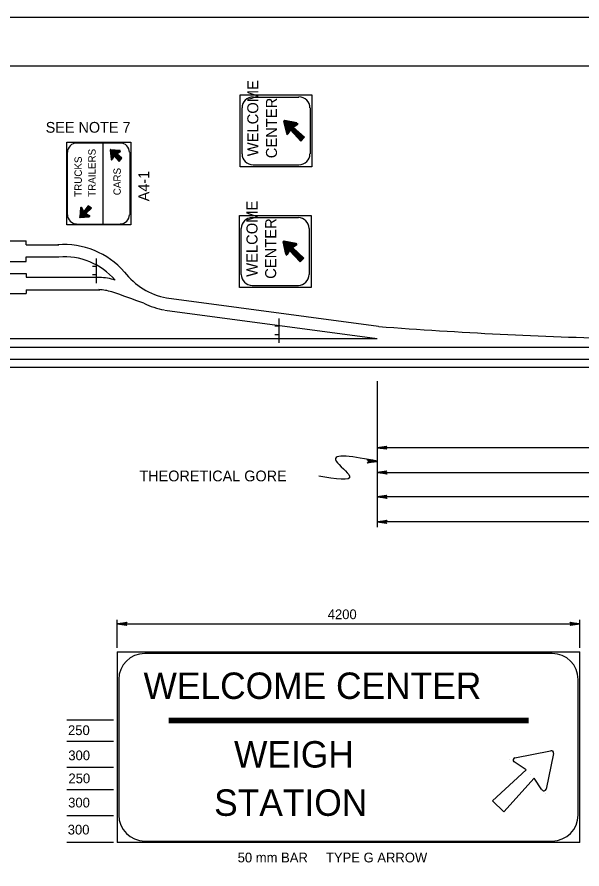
# Model space of a CAD drawing. Extents: x 638689 to 652291, y 298458 to 299646.
# Drawn here: x 651569.7 to 651743.8, y 299383.4 to 299645.7 of the extents above; entities that cross this region are included whole.
import ezdxf

# ---------------------------------------------------------------- set-up
doc = ezdxf.new("R2010")
doc.units = 0
for name, color, linetype in [('1', 7, 'Continuous'), ('2', 7, 'Continuous'), ('3', 7, 'Continuous'), ('PLT-BNDY', 7, 'Continuous')]:
    doc.layers.add(name, color=color, linetype=linetype)

# ---------------------------------------------------------------- blocks, each defined once
blk = doc.blocks.new('RARROW')
at = {"layer": '3'}
blk.add_lwpolyline([(-2.2695, 0.285), (-2.184875, 0.12075), (0, 0), (-2.2695, 0.285), (-2.38575, 0.384625), (0, 0), (-2.183125, -0.108), (-2.262875, -0.2705), (0, 0), (-2.38575, -0.379125), (-2.262875, -0.2705)], dxfattribs=at)

msp = doc.modelspace()

# ---------------------------------------------------------------- linework, layer by layer
at = {"layer": '1'}
msp.add_line((651426.31, 299630.75), (652212.31, 299630.75), dxfattribs=at)
at = {"layer": '2'}
for p, q in [((651642.44, 299621.12), (651656.56, 299621.12)), ((651651.81, 299613.87), (651651.81, 299613.87)), ((651651.94, 299613.62), (651652.81, 299609.87)), ((651655.94, 299613.12), (651652.19, 299613.87)), ((651654.81, 299611.87), (651656.19, 299612.75)), ((651656.56, 299613), (651656.56, 299613)), ((651653.19, 299609.75), (651653.94, 299611)), ((651653.94, 299611), (651653.94, 299611)), ((651653.94, 299611), (651657.19, 299607.5)), ((651654.81, 299611.87), (651654.81, 299611.87)), ((651658.31, 299608.75), (651654.81, 299611.87)), ((651588.06, 299607), (651601.56, 299607)), ((651596.31, 299582), (651596.31, 299607)), ((651652.94, 299609.37), (651652.94, 299609.37)), ((651657.19, 299607.5), (651658.31, 299608.75)), ((651598.44, 299604.75), (651598.69, 299602)), ((651601.44, 299604.62), (651598.56, 299604.87)), ((651598.56, 299604.75), (651598.56, 299604.75)), ((651600.44, 299603.62), (651601.44, 299604.25)), ((651601.44, 299604.37), (651601.44, 299604.37)), ((651601.69, 299604.37), (651601.69, 299604.37)), ((651601.69, 299604.37), (651601.69, 299604.37)), ((651598.81, 299602), (651598.81, 299602)), ((651598.81, 299601.62), (651598.81, 299601.62)), ((651598.81, 299601.62), (651598.81, 299601.62)), ((651599.69, 299603), (651599.06, 299602)), ((651599.69, 299603), (651599.69, 299603)), ((651599.69, 299603), (651601.19, 299601.25)), ((651600.06, 299603.37), (651600.06, 299603.37)), ((651600.44, 299603.62), (651600.44, 299603.62)), ((651602.06, 299602.25), (651600.44, 299603.62)), ((651601.19, 299601.25), (651602.06, 299602.25)), ((651602.06, 299602.25), (651602.06, 299602.25)), ((651601.19, 299601.25), (651601.19, 299601.25)), ((651660.56, 299599.62), (651638.44, 299599.62)), ((651656.56, 299600.12), (651642.44, 299600.12)), ((651589.31, 299587), (651589.06, 299584.25)), ((651589.56, 299587.25), (651589.56, 299587.25)), ((651589.56, 299587.25), (651589.56, 299587.25)), ((651589.56, 299587), (651589.56, 299587)), ((651590.31, 299585.87), (651589.69, 299587.12)), ((651591.69, 299587.62), (651590.31, 299585.87)), ((651590.94, 299585.25), (651592.69, 299586.87)), ((651591.69, 299587.62), (651591.69, 299587.62)), ((651592.69, 299586.87), (651591.69, 299587.62)), ((651592.69, 299586.87), (651592.69, 299586.87)), ((651589.06, 299584.12), (651589.06, 299584.12)), ((651589.06, 299584.12), (651589.06, 299584.12)), ((651589.19, 299584.25), (651589.19, 299584.25)), ((651589.19, 299584), (651591.94, 299584.25)), ((651590.31, 299585.87), (651590.31, 299585.87)), ((651590.56, 299585.62), (651590.56, 299585.62)), ((651590.94, 299585.25), (651590.94, 299585.25)), ((651590.94, 299585.25), (651591.94, 299584.62)), ((651591.94, 299584.5), (651591.94, 299584.5)), ((651592.19, 299584.5), (651592.19, 299584.5)), ((651592.19, 299584.5), (651592.19, 299584.5)), ((651642.19, 299584), (651656.44, 299584)), ((651587.69, 299581.75), (651585.81, 299581.75)), ((651588.06, 299582), (651601.56, 299582)), ((651596.81, 299581.75), (651595.44, 299581.75)), ((651549.94, 299576.87), (651572.56, 299576.87)), ((651572.56, 299575.62), (651572.56, 299576.87)), ((651572.56, 299575.62), (651582.56, 299575.62)), ((651651.56, 299576.75), (651651.56, 299576.75)), ((651651.69, 299576.5), (651652.56, 299572.75)), ((651655.69, 299576), (651651.94, 299576.75)), ((651654.56, 299574.75), (651655.81, 299575.62)), ((651656.31, 299575.87), (651656.31, 299575.87)), ((651652.94, 299572.62), (651653.69, 299573.87)), ((651653.69, 299573.87), (651653.69, 299573.87)), ((651653.69, 299573.87), (651656.94, 299570.37)), ((651654.56, 299574.75), (651654.56, 299574.75)), ((651658.06, 299571.5), (651654.56, 299574.75)), ((651549.94, 299570.5), (651572.56, 299570.5)), ((651572.56, 299570.5), (651572.56, 299571.87)), ((651572.56, 299571.87), (651582.56, 299571.87)), ((651594.19, 299563.75), (651594.19, 299571.37)), ((651652.69, 299572.25), (651652.69, 299572.25)), ((651656.94, 299570.37), (651658.06, 299571.5)), ((651594.19, 299568.87), (651592.94, 299568.87)), ((651549.94, 299566.75), (651572.56, 299566.75)), ((651572.56, 299566.75), (651572.56, 299565.62)), ((651572.56, 299565.62), (651595.19, 299565.62)), ((651594.19, 299566.37), (651592.94, 299566.37)), ((651660.31, 299562.5), (651638.31, 299562.5)), ((651656.44, 299563), (651642.19, 299563)), ((651549.94, 299560.62), (651572.56, 299560.62)), ((651572.56, 299561.75), (651572.56, 299560.62)), ((651572.56, 299561.75), (651595.19, 299561.75)), ((651615.81, 299559.25), (651681.06, 299550.5)), ((651615.31, 299555.5), (651615.31, 299555.5)), ((651615.31, 299555.5), (651680.69, 299546.75)), ((651650.44, 299545.37), (651650.44, 299552.87)), ((651650.44, 299550.5), (651649.19, 299550.5)), ((651441.81, 299546.75), (651680.69, 299546.75)), ((651650.44, 299547.87), (651649.19, 299547.87)), ((651680.69, 299546.75), (651680.69, 299546.75)), ((651680.69, 299546.75), (651680.69, 299546.75)), ((651429.31, 299544.12), (652211.31, 299544.12)), ((651429.31, 299540.37), (652211.31, 299540.37)), ((651429.31, 299537.87), (652211.31, 299537.87)), ((651680.69, 299533.62), (651680.69, 299488.62)), ((651917.06, 299513.12), (651680.69, 299513.12)), ((651680.69, 299505.5), (652031.94, 299505.5)), ((652084.69, 299498), (651680.69, 299498)), ((652137.56, 299490.25), (651680.69, 299490.25)), ((651600.58, 299451.48), (651600.58, 299460.1)), ((651743.08, 299451.48), (651743.08, 299460.1)), ((651600.58, 299458.85), (651743.08, 299458.85)), ((651600.58, 299450.23), (651743.08, 299450.23)), ((651600.58, 299450.23), (651600.58, 299391.48)), ((651734.58, 299449.73), (651609.08, 299449.73)), ((651743.08, 299391.48), (651743.08, 299450.23)), ((651601.08, 299441.73), (651601.08, 299399.98)), ((651742.58, 299399.98), (651742.58, 299441.73)), ((651599.45, 299429.23), (651585.09, 299429.23)), ((651616.45, 299429.85), (651727.33, 299429.85)), ((651616.45, 299429.6), (651727.33, 299429.6)), ((651616.45, 299429.23), (651727.33, 299429.23)), ((651616.45, 299428.98), (651727.33, 299428.98)), ((651616.45, 299428.73), (651727.33, 299428.73)), ((651616.45, 299428.48), (651727.33, 299428.48)), ((651599.45, 299422.6), (651585.09, 299422.6)), ((651723.08, 299417.6), (651734.08, 299419.73)), ((651734.95, 299418.98), (651732.7, 299407.98)), ((651734.95, 299418.98), (651732.7, 299407.98)), ((651735.08, 299419.98), (651735.08, 299419.98)), ((651721.58, 299417.23), (651721.58, 299417.23)), ((651726.58, 299413.85), (651722.83, 299416.35)), ((651726.58, 299413.85), (651722.83, 299416.35)), ((651599.45, 299414.6), (651585.09, 299414.6)), ((651716.2, 299404.35), (651726.58, 299413.85)), ((651716.2, 299404.35), (651726.58, 299413.85)), ((651726.58, 299413.85), (651726.58, 299413.85)), ((651729.08, 299411.35), (651719.7, 299400.98)), ((651729.08, 299411.35), (651719.7, 299400.98)), ((651727.83, 299412.6), (651727.83, 299412.6)), ((651731.45, 299407.73), (651729.08, 299411.35)), ((651729.08, 299411.35), (651729.08, 299411.35)), ((651599.45, 299407.73), (651585.09, 299407.73)), ((651732.45, 299406.48), (651732.45, 299406.48)), ((651719.7, 299400.98), (651716.2, 299404.35)), ((651719.7, 299400.98), (651716.2, 299404.35)), ((651716.2, 299404.35), (651716.2, 299404.35)), ((651599.45, 299399.73), (651585.09, 299399.73)), ((651719.7, 299400.98), (651719.7, 299400.98)), ((651609.08, 299391.98), (651734.58, 299391.98)), ((651599.45, 299391.48), (651585.09, 299391.48)), ((651743.08, 299391.48), (651600.58, 299391.48))]:
    msp.add_line(p, q, dxfattribs=at)
for points in [[(651638.44, 299599.62), (651638.44, 299621.75), (651640.69, 299621.75), (651644.06, 299621.75), (651646.44, 299621.75), (651649.81, 299621.75), (651651.81, 299621.75), (651658.44, 299621.75), (651660.56, 299621.75), (651660.56, 299621.75), (651660.56, 299599.62), (651660.56, 299599.62)], [(651639.06, 299603.62), (651639.06, 299617.75)], [(651660.06, 299617.75), (651660.06, 299603.62)], [(651657.19, 299607.5), (651653.94, 299611), (651653.19, 299609.75), (651652.94, 299609.75), (651652.81, 299609.87), (651651.94, 299613.62), (651652.06, 299613.75), (651652.19, 299613.87), (651655.94, 299613), (651656.19, 299612.87), (651655.94, 299612.75), (651654.69, 299611.87), (651658.31, 299608.75), (651657.19, 299607.5), (651653.94, 299611.12), (651653.06, 299609.75), (651652.94, 299609.75), (651652.94, 299609.87), (651652.06, 299613.62), (651652.06, 299613.75), (651652.19, 299613.75), (651655.94, 299613), (651655.94, 299612.87), (651655.94, 299612.75), (651654.69, 299611.87), (651658.19, 299608.75), (651657.19, 299607.62), (651653.94, 299611.12), (651653.06, 299609.87), (651652.94, 299609.87), (651652.94, 299609.87), (651652.06, 299613.75), (651655.94, 299612.87), (651654.56, 299611.87), (651658.06, 299608.62), (651657.19, 299607.75), (651653.94, 299611.25), (651652.94, 299609.87), (651652.19, 299613.62)], [(651653.06, 299610), (651652.19, 299613.75), (651655.94, 299612.87), (651654.44, 299611.87), (651658.06, 299608.62), (651657.19, 299607.75), (651653.94, 299611.25), (651653.06, 299610.12), (651652.44, 299613.62), (651655.81, 299612.87), (651654.44, 299611.87), (651657.94, 299608.62), (651657.19, 299607.87), (651653.94, 299611.37), (651653.06, 299610.25), (651652.44, 299613.5), (651655.56, 299612.75), (651654.31, 299611.87), (651657.81, 299608.62), (651657.19, 299608.12), (651653.94, 299611.37), (651653.19, 299610.5), (651652.56, 299613.37), (651655.31, 299612.75), (651654.19, 299611.87), (651657.69, 299608.75), (651657.19, 299608.12), (651653.94, 299611.5), (651653.19, 299610.75), (651652.69, 299613.25), (651655.19, 299612.75), (651654.06, 299611.87), (651657.56, 299608.75), (651657.19, 299608.25), (651653.94, 299611.62), (651653.19, 299610.87), (651652.81, 299613.12), (651654.94, 299612.62), (651654.06, 299611.87), (651657.44, 299608.75), (651657.44, 299608.75), (651657.19, 299608.5), (651653.81, 299611.62), (651653.31, 299611), (651652.94, 299613.12), (651654.81, 299612.62), (651653.94, 299611.87), (651657.31, 299608.62), (651657.19, 299608.62), (651653.94, 299611.75), (651653.31, 299611.25), (651652.94, 299613), (651654.56, 299612.62), (651653.94, 299611.87), (651657.31, 299608.62), (651657.19, 299608.62), (651653.94, 299611.87), (651653.44, 299611.37), (651653.06, 299612.87), (651654.56, 299612.5), (651653.44, 299611.5), (651653.19, 299612.75), (651654.31, 299612.5), (651653.44, 299611.62), (651653.31, 299612.62), (651654.19, 299612.5), (651653.44, 299611.75), (651653.31, 299612.62), (651654.06, 299612.37), (651653.56, 299612), (651653.44, 299612.5), (651653.81, 299612.37), (651653.56, 299612.25), (651653.56, 299612.37), (651653.69, 299612.37)], [(651585.06, 299581.75), (651585.06, 299607.25), (651586.81, 299607.25), (651589.06, 299607.25), (651590.69, 299607.25), (651593.06, 299607.25), (651594.69, 299607.25), (651596.56, 299607.25), (651600.31, 299607.25), (651604.81, 299607.25), (651604.81, 299581.75), (651599.44, 299581.75), (651597.31, 299581.75), (651594.69, 299581.75), (651591.81, 299581.75), (651588.06, 299581.75), (651585.06, 299581.75)], [(651598.44, 299604.75), (651598.81, 299602.12), (651598.81, 299602), (651598.94, 299601.87), (651598.94, 299602), (651599.69, 299603.12), (651599.69, 299603.12), (651601.19, 299601.37), (651601.94, 299602.25), (651600.31, 299603.62), (651600.31, 299603.62), (651601.44, 299604.37), (651601.56, 299604.37), (651601.44, 299604.5), (651601.44, 299604.5), (651598.56, 299604.87), (651598.56, 299604.87), (651598.44, 299604.75), (651598.56, 299604.75), (651598.81, 299602), (651599.56, 299603.12), (651601.19, 299601.5), (651601.94, 299602.25), (651600.19, 299603.62), (651601.44, 299604.5), (651598.56, 299604.75), (651598.81, 299602.12), (651599.56, 299603.25), (651601.19, 299601.5), (651601.81, 299602.25), (651600.19, 299603.62), (651601.44, 299604.37), (651598.56, 299604.75), (651598.94, 299602.25), (651599.56, 299603.25), (651601.19, 299601.62), (651601.69, 299602.25), (651600.19, 299603.62), (651601.31, 299604.37), (651598.69, 299604.62), (651598.94, 299602.37), (651599.56, 299603.37), (651601.19, 299601.62), (651601.69, 299602.25), (651600.06, 299603.62), (651601.19, 299604.37), (651598.69, 299604.62), (651598.94, 299602.5), (651599.56, 299603.37), (651601.19, 299601.87), (651601.56, 299602.25), (651600.06, 299603.62), (651600.94, 299604.37), (651598.81, 299604.62), (651599.06, 299602.62), (651599.56, 299603.5), (651601.19, 299602), (651601.56, 299602.25), (651599.94, 299603.62), (651600.94, 299604.25), (651598.81, 299604.5), (651599.06, 299602.75), (651599.56, 299603.5), (651601.19, 299602), (651601.44, 299602.25), (651599.94, 299603.75), (651600.69, 299604.25), (651598.81, 299604.5), (651599.06, 299602.87), (651599.56, 299603.62), (651601.19, 299602.12), (651601.44, 299602.25), (651599.94, 299603.75), (651600.56, 299604.25), (651598.94, 299604.37), (651599.06, 299603), (651599.56, 299603.62), (651601.19, 299602.12), (651601.31, 299602.25), (651599.69, 299603.75), (651600.44, 299604.12), (651599.06, 299604.37), (651599.19, 299603.25), (651599.56, 299603.75), (651601.19, 299602.25), (651601.31, 299602.25), (651599.69, 299603.75), (651600.31, 299604.12), (651599.06, 299604.25), (651599.19, 299603.37), (651599.56, 299603.75), (651601.19, 299602.25), (651599.56, 299603.87), (651600.19, 299604.12), (651599.06, 299604.25), (651599.19, 299603.37), (651599.56, 299603.87), (651600.44, 299603.12), (651599.56, 299603.87), (651600.19, 299604.12), (651599.19, 299604.12)], [(651585.31, 299584.87), (651585.31, 299604.12)], [(651599.19, 299604.12), (651599.19, 299603.62), (651600.06, 299604.12), (651599.19, 299604.12), (651599.31, 299603.62), (651599.94, 299604), (651599.31, 299604.12), (651599.31, 299603.75), (651599.69, 299604), (651599.31, 299604), (651599.31, 299603.87), (651599.56, 299604), (651599.31, 299604), (651599.31, 299603.87), (651599.44, 299604)], [(651604.44, 299604.12), (651604.44, 299584.87)], [(651589.19, 299584.12), (651591.81, 299584.37), (651591.94, 299584.37), (651592.06, 299584.5), (651591.94, 299584.62), (651590.81, 299585.25), (651590.81, 299585.37), (651592.56, 299586.87), (651591.69, 299587.62), (651590.31, 299585.87), (651590.31, 299585.87), (651589.56, 299587.12), (651589.56, 299587.12), (651589.44, 299587.12), (651589.44, 299587), (651589.06, 299584.25), (651589.06, 299584.12), (651589.19, 299584.12), (651589.19, 299584.12), (651591.94, 299584.5), (651590.81, 299585.25), (651592.44, 299586.87), (651591.69, 299587.5), (651590.31, 299585.75), (651589.44, 299587.12), (651589.19, 299584.12), (651591.81, 299584.5), (651590.69, 299585.25), (651592.44, 299586.87), (651591.69, 299587.37), (651590.31, 299585.75), (651589.56, 299587), (651589.19, 299584.25), (651591.69, 299584.5), (651590.69, 299585.25), (651592.19, 299586.87), (651591.69, 299587.37), (651590.31, 299585.62), (651589.56, 299586.87), (651589.31, 299584.25), (651591.56, 299584.62), (651590.56, 299585.25), (651592.19, 299586.87), (651591.69, 299587.37), (651590.31, 299585.62), (651589.56, 299586.62), (651589.31, 299584.37), (651591.44, 299584.62), (651590.56, 299585.25), (651592.06, 299586.87), (651591.69, 299587.25), (651590.31, 299585.5), (651589.56, 299586.5), (651589.31, 299584.37), (651591.31, 299584.62), (651590.44, 299585.25), (651591.94, 299586.87), (651591.69, 299587.12), (651590.31, 299585.5), (651589.69, 299586.37), (651589.44, 299584.5), (651591.19, 299584.75), (651590.44, 299585.25), (651591.94, 299586.87), (651591.69, 299587.12), (651590.19, 299585.5), (651589.69, 299586.25), (651589.44, 299584.5), (651591.06, 299584.75), (651590.31, 299585.25), (651591.81, 299586.87), (651591.69, 299587), (651590.19, 299585.37), (651589.69, 299586.12), (651589.56, 299584.5), (651590.81, 299584.75), (651590.31, 299585.25), (651591.81, 299586.87), (651591.69, 299587), (651590.19, 299585.37), (651589.81, 299586), (651589.56, 299584.62), (651590.69, 299584.75), (651590.19, 299585.25), (651591.69, 299586.87), (651591.69, 299586.87), (651590.19, 299585.25), (651589.81, 299585.87), (651589.69, 299584.75), (651590.56, 299584.75), (651590.19, 299585.25), (651591.69, 299586.87), (651590.06, 299585.25), (651589.81, 299585.75), (651589.69, 299584.75), (651590.56, 299584.87), (651590.06, 299585.12), (651590.81, 299585.87), (651590.06, 299585.25), (651589.81, 299585.62), (651589.81, 299584.75)], [(651589.81, 299584.75), (651590.31, 299584.87), (651589.81, 299585.5), (651589.81, 299584.87), (651590.31, 299584.87), (651589.94, 299585.5), (651589.81, 299584.87), (651590.19, 299585), (651589.94, 299585.25), (651589.94, 299585), (651590.06, 299585), (651589.94, 299585.25), (651589.94, 299585), (651590.06, 299585), (651589.94, 299585.12)], [(651638.31, 299562.5), (651638.31, 299584.62), (651640.44, 299584.62), (651643.81, 299584.62), (651646.19, 299584.62), (651649.56, 299584.62), (651651.56, 299584.62), (651658.19, 299584.62), (651660.31, 299584.62), (651660.31, 299584.62), (651660.31, 299562.5), (651660.31, 299562.5)], [(651638.81, 299566.5), (651638.81, 299580.62)], [(651659.69, 299580.62), (651659.69, 299566.5)], [(651656.94, 299570.37), (651653.69, 299573.87), (651652.94, 299572.62), (651652.81, 299572.62), (651652.56, 299572.75), (651651.69, 299576.5), (651651.81, 299576.62), (651651.94, 299576.75), (651655.69, 299575.87), (651655.81, 299575.75), (651655.81, 299575.62), (651654.56, 299574.75), (651658.06, 299571.5), (651656.94, 299570.37), (651653.69, 299574), (651652.81, 299572.62), (651652.81, 299572.62), (651652.69, 299572.75), (651651.81, 299576.5), (651651.81, 299576.62), (651651.94, 299576.62), (651655.69, 299575.87), (651655.81, 299575.75), (651655.69, 299575.62), (651654.44, 299574.75), (651657.94, 299571.5), (651656.94, 299570.5), (651653.69, 299574), (651652.81, 299572.75), (651652.69, 299572.75), (651652.69, 299572.75), (651651.81, 299576.62), (651655.69, 299575.75), (651654.44, 299574.75), (651657.94, 299571.37), (651656.94, 299570.62), (651653.69, 299574), (651652.81, 299572.75), (651651.94, 299576.5)], [(651652.81, 299572.87), (651651.94, 299576.62), (651655.69, 299575.75), (651654.31, 299574.75), (651657.81, 299571.37), (651656.94, 299570.62), (651653.69, 299574.12), (651652.81, 299573), (651652.06, 299576.5), (651655.56, 299575.75), (651654.19, 299574.75), (651657.81, 299571.37), (651656.94, 299570.75), (651653.69, 299574.25), (651652.94, 299573.12), (651652.06, 299576.37), (651655.31, 299575.62), (651654.06, 299574.75), (651657.69, 299571.37), (651656.94, 299570.87), (651653.69, 299574.25), (651652.94, 299573.37), (651652.19, 299576.25), (651655.06, 299575.62), (651653.94, 299574.75), (651657.44, 299571.37), (651656.94, 299571), (651653.69, 299574.37), (651652.94, 299573.62), (651652.44, 299576.12), (651654.94, 299575.62), (651653.94, 299574.75), (651657.31, 299571.37), (651656.94, 299571.12), (651653.69, 299574.5), (651653.06, 299573.75), (651652.56, 299576), (651654.69, 299575.37), (651653.81, 299574.75), (651657.19, 299571.5), (651657.19, 299571.5), (651656.94, 299571.25), (651653.69, 299574.5), (651653.06, 299573.87), (651652.69, 299576), (651654.56, 299575.37), (651653.81, 299574.75), (651657.19, 299571.37), (651656.94, 299571.37), (651653.69, 299574.62), (651653.06, 299574.12), (651652.69, 299575.87), (651654.44, 299575.37), (651653.69, 299574.75), (651657.06, 299571.37), (651656.94, 299571.37), (651653.69, 299574.75), (651653.19, 299574.25), (651652.81, 299575.75), (651654.31, 299575.25), (651653.19, 299574.37), (651652.94, 299575.62), (651654.19, 299575.25), (651653.19, 299574.5), (651653.06, 299575.37), (651654.06, 299575.25), (651653.31, 299574.62), (651653.19, 299575.37), (651653.81, 299575.12), (651653.31, 299574.87), (651653.19, 299575.25), (651653.69, 299575.12), (651653.44, 299575), (651653.31, 299575.12), (651653.44, 299575.12)]]:
    msp.add_lwpolyline(points, dxfattribs=at)
for centre, radius, start, end in [((651642.43, 299617.76), 3.39, 90, 180), ((651656.57, 299617.76), 3.39, 0, 90), ((651652.18, 299613.66), 0.212, 78.0958, 191.9043), ((651652.18, 299613.66), 0.212, 78.0958, 191.9043), ((651655.98, 299612.86), 0.212, 302.692, 78.0958), ((651655.98, 299612.86), 0.212, 302.692, 78.0958), ((651652.98, 299609.86), 0.212, 191.9042, 327.308), ((651652.98, 299609.86), 0.212, 191.9043, 327.308), ((651588.1, 299604.1), 2.83, 90, 180), ((651601.55, 299604.1), 2.83, 0, 90), ((651598.6, 299604.75), 0.177, 84.0498, 185.9502), ((651601.38, 299604.46), 0.177, 301.5539, 84.0498), ((651598.89, 299601.98), 0.177, 185.9502, 328.4461), ((651642.43, 299603.62), 3.39, 180, 270), ((651656.57, 299603.62), 3.39, 270, 0), ((651589.47, 299586.95), 0.177, 31.5539, 174.0498), ((651588.1, 299584.87), 2.83, 180, 270), ((651589.18, 299584.17), 0.177, 174.0498, 275.9502), ((651591.95, 299584.46), 0.177, 275.9502, 58.4461), ((651601.55, 299584.87), 2.83, 270, 0), ((651642.2, 299580.61), 3.39, 90, 180), ((651656.34, 299580.61), 3.39, 0, 90), ((651584.26, 299551.14), 24.54, 40.8957, 94.5866), ((651651.95, 299576.51), 0.212, 78.0958, 191.9043), ((651651.95, 299576.51), 0.212, 78.0958, 191.9043), ((651655.75, 299575.71), 0.212, 302.692, 78.0958), ((651655.75, 299575.71), 0.212, 302.692, 78.0958), ((651584.26, 299551.14), 20.77, 40.8957, 94.5866), ((651652.75, 299572.71), 0.212, 191.9042, 327.308), ((651652.75, 299572.71), 0.212, 191.9043, 327.308), ((651594.11, 299544.96), 20.62, 73.5134, 87.0474), ((651619.81, 299580.34), 21.48, 217.6891, 259.2048), ((651642.2, 299566.47), 3.39, 180, 270), ((651656.34, 299566.47), 3.39, 270, 0), ((651594.11, 299544.96), 16.85, 73.5134, 87.0474), ((649004.06, 292218.64), 7787.51, 70.459164, 70.536636), ((651619.81, 299580.34), 25.25, 244.1957, 259.2048), ((651789.98, 300979.53), 1433.22, 265.6447, 268.64351), ((651609.08, 299441.73), 8, 90, 180), ((651734.58, 299441.73), 8, 0, 90), ((651734.32, 299419.13), 0.686, 348.2602, 101.7398), ((651734.32, 299419.13), 0.686, 348.2602, 101.7398), ((651723.2, 299416.91), 0.675, 101.0564, 236.3099), ((651732.04, 299408.11), 0.686, 213.3162, 348.2602), ((651732.04, 299408.11), 0.686, 213.3162, 348.2602), ((651609.08, 299399.98), 8, 180, 270), ((651734.58, 299399.98), 8, 270, 0)]:
    msp.add_arc(centre, radius, start, end, dxfattribs=at)
msp.add_spline([(651680.69, 299509), (651668.06, 299509), (651672.19, 299504.37), (651662.7, 299504.37)], degree=3, dxfattribs=at)
at = {"layer": 'PLT-BNDY'}
msp.add_lwpolyline([(651386.31, 299645.75), (652227.31, 299645.75), (652227.31, 299051.75), (651386.31, 299051.75)], close=True, dxfattribs=at)

# ---------------------------------------------------------------- block references
at = {"layer": '2', "xscale": 1.2574347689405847, "yscale": 1.3092961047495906, "rotation": 180}
for p in [(651680.69, 299513.12), (651680.69, 299505.5), (651680.69, 299498), (651680.69, 299490.25), (651600.58, 299458.85)]:
    msp.add_blockref('RARROW', p, dxfattribs=at)
at = {"layer": '2', "xscale": 1.2574347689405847, "yscale": 1.3092961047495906}
for p in [(651680.63, 299508.88), (651743.08, 299458.85)]:
    msp.add_blockref('RARROW', p, dxfattribs=at)

# ---------------------------------------------------------------- texts
at = {"layer": '2'}
for s, height, p in [('WELCOME', 3.392, (651644.06, 299602.87)), ('CENTER', 3.392, (651649.81, 299602.25)), ('TRAILERS', 2.261, (651593.94, 299590.37)), ('TRUCKS', 2.261, (651589.69, 299590.37)), ('CARS', 2.261, (651601.69, 299590.87)), ('A4-1', 3.318, (651610.44, 299589)), ('WELCOME', 3.392, (651643.81, 299565.75)), ('CENTER', 3.392, (651649.56, 299565.12))]:
    msp.add_text(s, height=height, rotation=90, dxfattribs=at).set_placement(p)
for s, height, p in [('SEE NOTE 7', 3.317, (651578.56, 299610.12)), ('THEORETICAL GORE', 3.3173, (651607.44, 299502.75)), ('4200', 3, (651665.44, 299460.3)), ('WELCOME CENTER', 8.1435, (651608.7, 299435.73)), ('250', 3, (651585.44, 299424.6)), ('WEIGH', 8.143, (651636.58, 299414.6)), ('300', 3, (651585.53, 299416.86)), ('250', 3, (651585.57, 299409.77)), ('STATION', 8.143, (651630.45, 299399.73)), ('300', 3, (651585.48, 299402.31)), ('300', 3, (651585.35, 299393.98)), ('50 mm BAR     TYPE G ARROW', 3, (651637.7, 299385.39))]:
    msp.add_text(s, height=height, dxfattribs=at).set_placement(p)

doc.saveas('drawing.dxf')
